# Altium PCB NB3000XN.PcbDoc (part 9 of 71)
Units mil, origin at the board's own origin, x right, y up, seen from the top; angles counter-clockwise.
Board outline 9527.56 x 6929.77 mil, 6 copper layers (Top Layer, GND+SHIELD, MidLayer1, MidLayer2, P2 - 3V3+5V0, Bottom Layer), stack 62.375 mil thick; 832 components, 1027 nets, 4655 pads, 4981 vias.
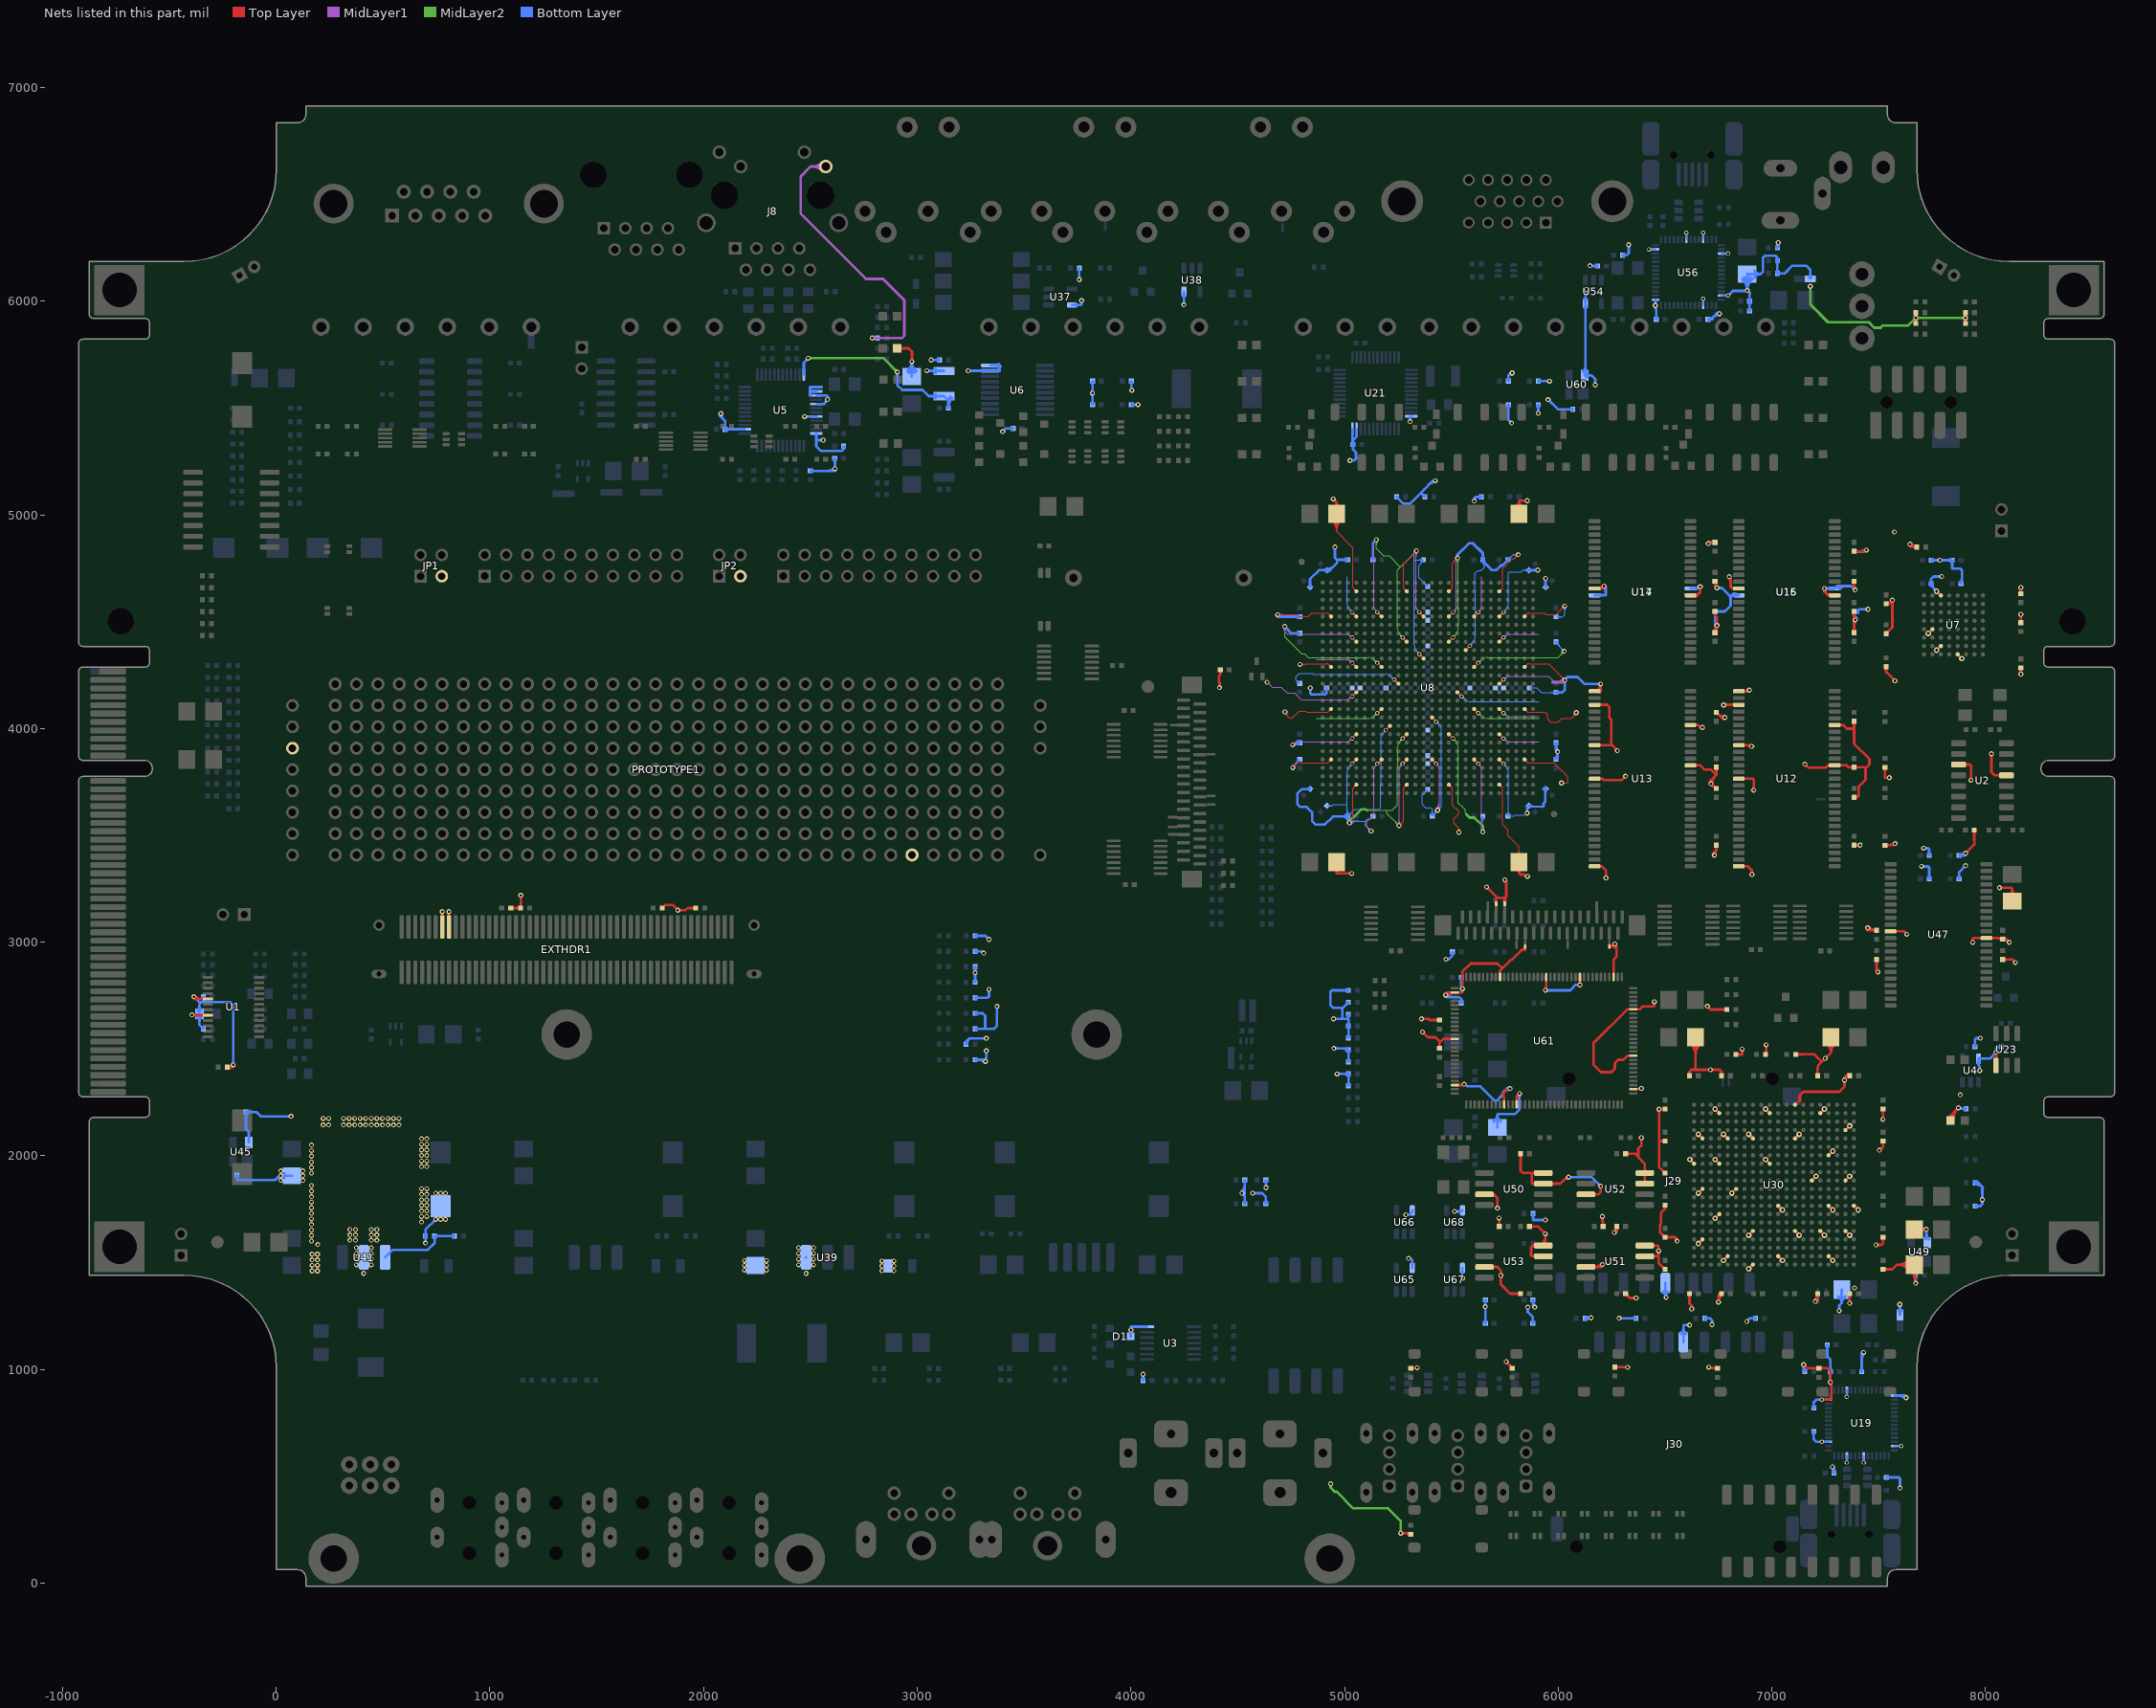
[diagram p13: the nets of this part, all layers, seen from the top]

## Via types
v1: diameter 23, hole 11.81, Top Layer to Bottom Layer, 3672 vias
v2: diameter 26, hole 11.81, Top Layer to Bottom Layer, 461 vias
v3: diameter 19, hole 11.81, Top Layer to Bottom Layer, tented both sides, 396 vias
v4: diameter 23.62, hole 11.81, Top Layer to Bottom Layer, 288 vias
v5: diameter 20, hole 11.81, Top Layer to Bottom Layer, 91 vias
v6: diameter 23, hole 11.81, Top Layer to Bottom Layer, tented both sides, 50 vias
v7: diameter 31, hole 11.81, Top Layer to Bottom Layer, 15 vias
v8: diameter 27.56, hole 11.81, Top Layer to Bottom Layer, tented both sides, 4 vias
v9: diameter 29, hole 11.81, Top Layer to Bottom Layer, 3 vias
v10: diameter 21, hole 11.81, Top Layer to Bottom Layer, 1 vias

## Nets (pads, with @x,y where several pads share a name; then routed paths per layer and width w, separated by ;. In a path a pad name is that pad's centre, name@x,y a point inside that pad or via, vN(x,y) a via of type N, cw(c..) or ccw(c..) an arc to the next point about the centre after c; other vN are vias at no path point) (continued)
3V3: (continued)
  Bottom Layer w12: v1@-385,2739.5 cw(c-385,2726.22) -375.61,2735.61 cw(c-366.22,2745) v1@-379.5,2745 ; v1(-385,2745) -354.99,2714.99 ; C20.1@-369.05,2650.4 cw(c-392.41,2627.04) -359.37,2627.04 cw(c-326.33,2627.04) C20.1@-349.69,2650.4 ; C20.1@-369.05,2679.6 ccw(c-392.41,2702.96) -359.37,2702.96 ccw(c-326.33,2702.96) C20.1@-349.69,2679.6 ; R21.1@-351.1,2604.92 ccw(c-341.18,2614.84) R21.1@-341.18,2600.81 ; R21.1@-349.91,2603.73 cw(c-358.15,2595.49) R21.1@-346.5,2595.49 ; C21.1@-344.78,2740.89 cw(c-354.7,2730.97) -340.67,2730.97 cw(c-326.64,2730.97) C21.1@-336.56,2740.89 ; R21.1@-341.18,2595 -359.37,2613.19 C20.1@-359.37,2665 -359.37,2710.6 -354.99,2714.99 ; C21.1@-340.67,2745 -340.67,2720.71 -340,2720.04 ; v1@-205.36,2429.6 ccw(c-214.75,2438.99) -201.48,2438.99 ccw(c-188.2,2438.99) v1@-197.59,2429.6 ; v1(-201.48,2425.71) -201.48,2705.04 -216.48,2720.04 -340,2720.04 ; R154.2@-187.44,1905.75 cw(c-196.52,1896.67) -183.68,1896.67 cw(c-170.84,1896.67) R154.2@-179.92,1905.75 ; R154.2@-183.68,1910 -183.68,1889.37 -181.68,1887.37 -109.81,1887.37 -4.81,1887.37 14.52,1906.71 14.52,1907.01 v1@21.14,1907.01 ; R98.2@-137.56,2201.24 cw(c-128.48,2192.16) -128.48,2205 cw(c-128.48,2217.84) R98.2@-137.56,2208.76 ; U45.4@-128.05,2063.31 -128.05,2113.05 -141.32,2126.32 R98.2@-141.32,2205 -93.1,2205 -92.81,2204.71 -73.1,2185 v1(70,2185) ; 1.81,1893.99 cw(c21.14,1874.66) v1@21.14,1902 ; v1@25.03,1903.61 cw(c33.23,1895.41) C136.1@33.23,1907.01 ; v1@25.03,1911.39 ccw(c35.61,1921.97) C136.1@35.61,1907.01 ; C136.1@37.85,1895.39 ccw(c21.14,1889.18) v1@21.14,1907.01 ; C136.1@37.85,1918.63 cw(c21.14,1924.83) v1@21.14,1907.01 ; v1@66.11,2181.11 ccw(c56.72,2171.72) 56.72,2185 ccw(c56.72,2198.28) v1@66.11,2188.89 ; C136.1@73.07,1907.01 v1@21.14,1907.01 ; v1@694.64,1595.6 ccw(c684.53,1605.7) 698.82,1605.7 ; R205.2@695.06,1620.75 cw(c685.98,1611.67) 698.82,1611.67 cw(c711.66,1611.67) R205.2@702.58,1620.75 ; R205.2@695.06,1629.25 ccw(c685.98,1638.33) 698.82,1638.33 ccw(c711.66,1638.33) R205.2@702.58,1629.25 ; v1(698.52,1591.71) 698.82,1592 R205.2@698.82,1625 698.82,1654.72 v1(747.01,1702.91) ; 698.82,1604.27 ccw(c711.09,1604.27) v1@702.41,1595.6 ; v1@741.51,1702.91 cw(c728.23,1702.91) 737.62,1693.52 cw(c747.01,1684.14) v1@747.01,1697.41 ; v1@2075.53,5476.54 ccw(c2087.64,5471.49) 2078.36,5462.21 ; v1(2081.52,5474.04) 2081.52,5459.04 2098.52,5442.04 2098.67,5442.04 2100.67,5440.04 C50.2@2100.67,5400 2102.09,5401.42 U5.14@2193.54,5401.42 ; v1@2086.6,5471.92 ccw(c2105.52,5464.03) 2091.02,5449.54 ; C50.2@2096.56,5404.11 ccw(c2086.64,5414.03) 2100.67,5414.03 ccw(c2114.7,5414.03) C50.2@2104.78,5404.11 ; C50.2@2104.78,5395.89 cw(c2118.12,5382.55) 2118.12,5401.42 ; v1@2470.52,5458.37 v1(2472.62,5460.47) U5.44@2528.19,5460.47 ; v1@2476.51,5456.58 cw(c2485.9,5447.19) 2485.9,5460.47 cw(c2485.9,5473.75) v1@2476.51,5464.36 ; U39.3@2479.81,1525.19 U39.3@2480,1525 ; 2498.52,5558.9 2498.52,5578.58 ; 2498.52,5563.77 cw(c2519.48,5563.77) 2504.66,5578.58 cw(c2519.48,5593.4) 2498.52,5593.4 ; 2498.52,5573.71 ccw(c2519.48,5573.71) U5.39@2504.66,5558.9 ; 2498.52,5583.45 cw(c2519.48,5583.45) U5.37@2504.66,5598.27 ; R50.2@2500,5206.18 2605.33,5206.18 v1(2615.19,5216.04) 2615.19,5264.14 C51.2@2614.33,5265 ; R50.2@2504.25,5202.42 cw(c2513.33,5193.34) 2513.33,5206.18 cw(c2513.33,5219.02) R50.2@2504.25,5209.94 ; U5.48@2527.52,5381.73 2527.52,5355 ; U5.41@2528.19,5519.53 2564.53,5519.53 v1(2580,5540.19) 2580,5555 2576.1,5558.9 U5.39@2528.19,5558.9 ; U5.38@2528.19,5578.58 2498.52,5578.58 ; U5.37@2551.71,5598.27 U5.37@2528.19,5598.27 2498.52,5598.27 2498.52,5578.58 ; v1@2556.11,5346.3 ccw(c2546.72,5336.92) 2546.72,5350.19 ccw(c2546.72,5363.47) v1@2556.11,5354.08 ; v1(2560,5350.19) 2532.33,5350.19 2527.52,5355 ; v1@2574.56,5539.41 cw(c2561.41,5537.52) 2572.04,5529.56 cw(c2582.67,5521.61) v1@2580.78,5534.75 ; 2578.11,5206.18 ccw(c2578.11,5253.12) 2611.3,5219.93 ccw(c2601.91,5229.32) 2615.19,5229.32 ccw(c2628.47,5229.32) v1@2619.08,5219.93 ; 2582.75,5552.25 cw(c2572.9,5542.4) v1@2586.21,5538.27 ; 2607.08,5206.18 ccw(c2607.08,5224.15) v1@2619.79,5211.44 ; C51.2@2610.22,5260.89 cw(c2598.23,5248.9) 2615.19,5248.9 ; 2615.19,5253.05 cw(c2626.28,5253.05) C51.2@2618.44,5260.89 ; R59.2@2652.42,5318.25 cw(c2643.34,5309.17) 2656.18,5309.17 cw(c2669.02,5309.17) R59.2@2659.94,5318.25 ; R59.2@2656.18,5322.5 2656.18,5308.37 2647.85,5300.04 2548.52,5300.04 2527.52,5321.04 2527.52,5355 ; v1(2789.7,5828) R57.2@2813.82,5828 ; v1@2793.59,5824.11 cw(c2802.98,5814.72) 2802.98,5828 cw(c2802.98,5841.28) v1@2793.59,5831.89 ; C49.1@2954.13,5674.03 ccw(c2919.27,5717.51) v1@2975,5717.51 ; C49.1@2961.63,5664.67 ccw(c2939.31,5692.51) 2975,5692.51 ccw(c3010.69,5692.51) C49.1@2988.37,5664.67 ; v1@2971.3,5713.82 cw(c2962.37,5704.89) 2975,5704.89 ; C49.1@2975,5647.99 v1@2975,5717.52 ; 2975,5703.97 cw(c2988.93,5703.97) v1@2979.08,5713.82 ; C49.1@2995.87,5674.03 cw(c3030.73,5717.51) v1@2975,5717.51 ; v1@3045,5675 3124.06,5675 L2.1@3125,5674.06 ; v1@3048.89,5671.3 cw(c3057.81,5662.38) 3057.81,5675 ; v1@3048.89,5679.08 ccw(c3058.75,5688.94) 3058.75,5675 ; 3060.15,5675 cw(c3060.15,5638.74) L2.1@3085.8,5664.38 ; 3064.72,5675 ccw(c3064.72,5704.81) L2.1@3085.8,5683.73 ; v1(3065,5725.19) C52.2@3104.33,5725 ; v1@3068.87,5721.29 cw(c3078.21,5711.85) 3078.28,5725.13 cw(c3078.34,5738.41) v1@3068.91,5729.06 ; C52.2@3100.2,5720.91 ccw(c3090.23,5711.04) 3090.3,5725.07 ccw(c3090.37,5739.1) C52.2@3100.24,5729.13 ; R226.2@3228.82,2522.5 3228.82,2533.86 3245,2550.04 ; R226.2@3234.14,2523.09 cw(c3271.24,2523.8) 3245,2550.04 ; v1(3238,5674.57) U6.19@3341.06,5674.57 3384.19,5674.57 3386.19,5676.57 3386.19,5698.49 3384.52,5700.16 U6.20@3341.06,5700.16 ; v1@3241.89,5670.68 cw(c3251.28,5661.29) 3251.28,5674.57 cw(c3251.28,5687.84) v1@3241.89,5678.46 ; v1@3267.3,2853.49 cw(c3257.93,2844.12) 3271.18,2844.12 ; v1@3267.3,2861.26 ccw(c3257.93,2870.63) 3271.18,2870.63 ; R224.2@3267.42,2816.75 ccw(c3258.34,2825.83) 3271.18,2825.83 ccw(c3284.02,2825.83) R224.2@3274.94,2816.75 ; R219.2@3267.42,2880.75 cw(c3258.34,2871.67) 3271.18,2871.67 cw(c3284.02,2871.67) R219.2@3274.94,2880.75 ; R232.2@3271.18,2450 v1@3319.48,2450 ; R227.2@3271.18,2595 3313.9,2595 ; R225.2@3271.18,2667.5 3305.92,2667.5 3317.92,2655.5 ; R218.2@3271.18,2740 3330,2740 3336.19,2746.19 v1(3336.19,2779.37) v1@3331.86,2775.04 ; R224.2@3271.18,2812.5 v1(3271.19,2857.37) R219.2@3271.18,2885 ; 3271.18,2844.07 cw(c3284.49,2844.07) v1@3275.08,2853.49 ; 3271.18,2870.67 ccw(c3284.49,2870.67) v1@3275.08,2861.26 ; R217.2@3271.18,2957.5 3302.73,2957.5 v1(3311.19,2949.04) ; R216.2@3271.18,3030 3319.23,3030 v1(3336.19,3013.04) ; R232.2@3274.94,2446.24 cw(c3284.02,2437.16) 3284.02,2450 cw(c3284.02,2462.84) R232.2@3274.94,2453.76 ; R227.2@3274.94,2591.24 cw(c3284.02,2582.16) 3284.02,2595 cw(c3284.02,2607.84) R227.2@3274.94,2598.76 ; R225.2@3274.94,2663.74 cw(c3284.02,2654.66) 3284.02,2667.5 cw(c3284.02,2680.34) R225.2@3274.94,2671.26 ; R218.2@3274.94,2736.24 cw(c3284.02,2727.16) 3284.02,2740 cw(c3284.02,2752.84) R218.2@3274.94,2743.76 ; R217.2@3274.94,2953.74 cw(c3284.02,2944.66) 3284.02,2957.5 cw(c3284.02,2970.34) R217.2@3274.94,2961.26 ; R216.2@3274.94,3026.24 cw(c3284.02,3017.16) 3284.02,3030 cw(c3284.02,3042.84) R216.2@3274.94,3033.76 ; 3286.23,2450 cw(c3286.23,2408.41) v1@3315.64,2437.82 ; v1@3315.64,2445.6 ccw(c3296.59,2464.64) 3323.52,2464.64 ; 3317.86,2655.37 3317.86,2598.96 3313.9,2595 ; v1(3319.52,2441.71) 3319.52,2450.04 v1@3319.48,2450 ; v1@3319.64,2487.82 cw(c3310.25,2478.43) 3323.52,2478.43 cw(c3336.8,2478.43) v1@3327.41,2487.82 ; v1@3319.64,2546.15 ccw(c3310.25,2536.76) 3310.25,2550.04 ccw(c3310.25,2563.32) v1@3319.64,2553.93 ; v1(3323.52,2491.71) 3323.52,2454.04 v1@3319.48,2450 ; v1(3323.52,2550.04) 3245,2550.04 ; v1@3330.69,3013.04 ccw(c3317.41,3013.04) 3326.8,3022.43 ccw(c3336.19,3031.82) v1@3336.19,3018.54 ; v1@3332.3,2775.49 cw(c3322.91,2766.1) 3336.19,2766.1 cw(c3349.47,2766.1) v1@3340.08,2775.49 ; v1@3369.64,2696.15 cw(c3360.25,2686.76) 3373.52,2686.76 cw(c3386.8,2686.76) v1@3377.41,2696.15 ; U6.20@3373,5697.74 cw(c3357.94,5673.84) 3386.19,5673.84 ; v1(3373.52,2700.04) 3373.52,2608.52 3360,2595 3313.9,2595 ; U6.20@3375.37,5697.43 cw(c3380.01,5682.31) 3391.19,5693.49 ; U6.20@3379.4,5707.89 cw(c3371.65,5695.59) 3386.19,5695.59 ; v1(3400,5390) 3415,5405 C54.2@3449.33,5405 ; C54.2@3445.22,5400.89 ccw(c3435.3,5390.97) 3435.3,5405 ccw(c3435.3,5419.03) C54.2@3445.22,5409.11 ; U37.5@3725.12,5982.6 3765.52,5982.6 3769.52,5986.6 v1(3769.52,6003.37) ; U37.5@3742.02,5978.49 cw(c3751.94,5968.57) 3751.94,5982.6 cw(c3751.94,5996.63) U37.5@3742.02,5986.71 ; v1@3754.79,6105.21 ccw(c3745.4,6114.6) 3758.68,6114.6 ccw(c3771.96,6114.6) v1@3762.57,6105.21 ; v1(3758.68,6101.32) R195.2@3758.68,6155 ; v1@3765.64,5999.49 cw(c3756.25,5990.1) 3769.52,5990.1 cw(c3782.8,5990.1) v1@3773.41,5999.49 ; C244.1@3816.28,5520.29 ccw(c3806.36,5530.21) 3820.39,5530.21 ccw(c3834.42,5530.21) C244.1@3824.5,5520.29 ; C243.1@3816.28,5622.07 cw(c3806.36,5612.15) 3820.39,5612.15 cw(c3834.42,5612.15) C243.1@3824.5,5622.07 ; v1@3816.5,5566.3 cw(c3807.11,5556.92) 3820.39,5556.92 cw(c3833.66,5556.92) v1@3824.28,5566.3 ; v1@3816.5,5574.08 ccw(c3807.11,5583.47) 3820.39,5583.47 ccw(c3833.66,5583.47) v1@3824.28,5574.08 ; C244.1@3820.39,5516.18 v1(3820.39,5570.19) C243.1@3820.39,5626.18 ; C229.1@3997.62,5622.07 cw(c3987.7,5612.15) 4001.73,5612.15 cw(c4015.75,5612.15) C229.1@4005.83,5622.07 ; D1.3@3999.21,1155 v1@3999.21,1175.04 ; v1(4000,1185) 4000,1200 U3.14@4076.5,1200 ; C259.1@4001.72,5516.18 v1@4033.82,5516.18 ; 4001.73,5603.41 ccw(c4024.56,5603.41) v1@4008.41,5587.26 ; C229.1@4001.72,5626.18 v1@4001.73,5586.17 ; C259.1@4005.83,5512.07 cw(c4015.75,5502.15) 4015.75,5516.18 cw(c4015.75,5530.21) C259.1@4005.83,5520.29 ; 4020.08,5516.18 ccw(c4020.08,5530.12) v1@4029.93,5520.26 ; 4021.01,5516.18 cw(c4021.01,5503.56) v1@4029.93,5512.48 ; C37.2@4053.22,953.11 ccw(c4043.3,963.03) 4057.33,963.03 ccw(c4071.36,963.03) C37.2@4061.44,953.11 ; v1@4053.44,973.78 cw(c4044.05,964.39) 4057.33,964.39 cw(c4070.61,964.39) v1@4061.22,973.78 ; C37.2@4057.33,949 v1(4057.33,977.67) ; U38.5@4244.33,6027.98 cw(c4234.41,6018.06) 4248.44,6018.06 cw(c4262.47,6018.06) U38.5@4252.55,6027.98 ; v1@4244.47,5986.95 ccw(c4234.88,5996.53) 4248.44,5996.53 ; v1(4248.36,5983.06) 4248.44,5983.14 U38.5@4248.44,6044.88 ; 4248.44,5996.13 ccw(c4261.44,5996.13) v1@4252.25,5986.95 ; v1@4516.11,1828.89 ccw(c4475.18,1869.82) 4533.06,1869.82 ; v1(4520,1825) 4533.06,1811.94 ; v1@4524.6,1820.4 ccw(c4504.15,1840.85) 4533.06,1840.85 ; C216.1@4528.95,1780.29 ccw(c4519.03,1790.21) 4533.06,1790.21 ccw(c4547.09,1790.21) C216.1@4537.17,1780.29 ; C232.1@4528.95,1882.07 cw(c4519.03,1872.15) 4533.06,1872.15 cw(c4547.09,1872.15) C232.1@4537.17,1882.07 ; C216.1@4533.06,1776.18 4533.06,1811.94 ; C232.1@4533.06,1886.18 4533.06,1825 4533.06,1811.94 ; v1(4570,1825) 4615,1825 4631.72,1808.28 C252.1@4631.72,1776.18 ; v1@4573.89,1821.11 cw(c4583.28,1811.72) 4583.28,1825 cw(c4583.28,1838.28) v1@4573.89,1828.89 ; C252.1@4627.62,1780.29 ccw(c4617.7,1790.21) 4631.72,1790.21 ccw(c4645.75,1790.21) C252.1@4635.83,1780.29 ; C251.1@4627.62,1882.07 cw(c4617.7,1872.15) 4631.72,1872.15 cw(c4645.75,1872.15) C251.1@4635.83,1882.07 ; v1@4630,1852 4631,1853 4631.72,1853.72 C251.1@4631.72,1886.18 ; 4631.72,1867.36 ccw(c4649.36,1867.36) v1@4636.89,1854.89 ; v1@4682.26,4528.78 ccw(c4694.61,4541.13) 4694.61,4523.66 ; v1(4686.86,4533.37) 4696.57,4523.66 C304.1@4790,4523.66 ; v1@4690.75,4537.26 ccw(c4723.58,4570.1) 4723.58,4523.66 ; v1@4720.19,4472.87 cw(c4720.19,4459.6) 4729.58,4468.99 cw(c4738.97,4478.37) v1@4725.69,4478.37 ; v1(4720.19,4478.37) 4739.19,4459.37 4739.19,4456.22 4748.52,4446.89 C320.1@4790,4446.89 ; v1(4757.52,3816.71) v1@4757.52,3824.04 ; v1@4758.52,3925.04 4765.19,3925.04 4765.19,3925.11 4773.19,3933.11 ; v1@4764.79,3924.71 cw(c4778.22,3911.27) C323.1@4787.24,3928 ; 4773.61,3933.53 cw(c4787.92,3919.22) C323.1@4790.92,3939.23 ; 4776.18,3936.1 cw(c4786.21,3926.08) C323.1@4792.94,3938.56 ; C320.1@4785.89,4442.78 ccw(c4775.97,4432.86) 4775.97,4446.89 ccw(c4775.97,4460.92) C320.1@4785.89,4451 ; C304.1@4785.89,4519.55 ccw(c4775.97,4509.63) 4775.97,4523.66 ccw(c4775.97,4537.69) C304.1@4785.89,4527.77 ; 4822.74,3716.71 ccw(c4822.74,3733.64) C327.1@4834.71,3721.67 ; C327.1@4826.84,3716.71 cw(c4826.84,3705.58) C327.1@4834.71,3713.45 ; C310.1@4834.71,4666.55 ccw(c4824.79,4676.47) 4838.82,4676.47 ccw(c4852.85,4676.47) C310.1@4842.93,4666.55 ; C327.1@4838.82,3717.56 4838.82,3716.71 4799.86,3716.71 4780,3696.85 4780,3644.9 4791.52,3633.37 4823.52,3633.37 4848.52,3608.37 4848.52,3566.71 4865.19,3550.04 4906.86,3550.04 4945.38,3588.57 C331.1@5003.57,3588.57 ; C310.1@4838.82,4662.44 4838.82,4700.04 ; 4838.86,4700.04 4880.52,4741.71 C294.1@4917.56,4741.71 ; v4(4840,4190) 4840,4165 4845,4160 4910,4160 4915.59,4165.59 C318.1@4915.59,4190 ; C294.1@4902.26,4741.71 cw(c4902.26,4725.88) C294.1@4913.45,4737.07 ; C294.1@4904.8,4741.71 ccw(c4904.8,4753.94) C294.1@4913.45,4745.29 ; C294.1@4917.56,4734.99 ccw(c4917.56,4752.94) C294.1@4930.25,4740.25 ; C294.1@4917.56,4741.18 4931.18,4741.18 4965,4775 4965,4790 ; C294.1@4917.56,4746.99 ccw(c4917.56,4793.91) 4950.73,4760.73 ; v1(4950,2503) 5011.27,2503 R240.2@5018.82,2495.45 R241.2@5018.82,2439.55 ; v1@4951.11,4846.11 cw(c4941.72,4836.72) 4955,4836.72 cw(c4968.28,4836.72) v1@4958.89,4846.11 ; v1@4953.89,2499.11 cw(c4963.28,2489.72) 4963.28,2503 cw(c4963.28,2516.28) v1@4953.89,2506.89 ; v1@4959.52,4846.04 4955.56,4850 v1(4955,4850) 4955,4800 4965,4790 ; v1(4965.19,2383.37) 4994.19,2383.37 4994.45,2383.64 R242.2@5018.82,2383.64 R243.2@5018.82,2327.73 R243.2@5018.82,2329.67 ; v1@4969.08,2379.49 cw(c4978.47,2370.1) 4978.47,2383.37 cw(c4978.47,2396.65) v1@4969.08,2387.26 ; 4986.86,2641.71 v1(4948.52,2641.71) 5017.11,2641.71 5018.82,2640 ; 4988.95,2503 cw(c4988.95,2466.08) R240.2@5015.06,2492.19 ; 4989.5,2645.73 4989.5,2686.91 ; 4997.51,3588.57 ccw(c4997.51,3607.49) C331.1@5010.89,3594.11 ; C331.1@5006.9,3585.23 cw(c4980.04,3558.37) v1@5018.02,3558.37 ; R236.2@5008.9,2709.17 cw(c5018.82,2699.25) R236.2@5018.82,2713.28 ; R236.2@5010.09,2710.36 ccw(c5001.85,2718.6) R236.2@5013.5,2718.6 ; C308.1@5010.89,4785.89 ccw(c5000.97,4775.97) 5000.97,4790 ccw(c5000.97,4804.03) C308.1@5010.89,4794.11 ; C331.1@5015,3590 5013.56,3588.57 C331.1@5003.57,3588.57 ; C308.1@5015,4790 4965,4790 ; R243.2@5015.06,2331.98 ccw(c5005.98,2341.06) 5018.82,2341.06 ccw(c5031.66,2341.06) R243.2@5022.58,2331.98 ; R242.2@5015.06,2379.38 cw(c5005.98,2370.3) 5018.82,2370.3 cw(c5031.66,2370.3) R242.2@5022.58,2379.38 ; R242.2@5015.06,2379.87 ccw(c5005.98,2370.8) 5005.98,2383.64 ccw(c5005.98,2396.48) R242.2@5015.06,2387.4 ; R241.2@5015.06,2443.8 ccw(c5005.98,2452.88) 5018.82,2452.88 ccw(c5031.66,2452.88) R241.2@5022.58,2443.8 ; R240.2@5015.06,2491.2 cw(c5005.98,2482.12) 5018.82,2482.12 cw(c5031.66,2482.12) R240.2@5022.58,2491.2 ; R239.2@5015.06,2555.62 ccw(c5005.98,2564.7) 5018.82,2564.7 ccw(c5031.66,2564.7) R239.2@5022.58,2555.62 ; R238.2@5015.06,2603.02 cw(c5005.98,2593.94) 5018.82,2593.94 cw(c5031.66,2593.94) R238.2@5022.58,2603.02 ; R238.2@5015.06,2611.53 ccw(c5005.98,2620.61) 5018.82,2620.61 ccw(c5031.66,2620.61) R238.2@5022.58,2611.53 ; R237.2@5015.06,2658.93 cw(c5005.98,2649.85) 5018.82,2649.85 cw(c5031.66,2649.85) R237.2@5022.58,2658.93 ; R260.2@5015.06,2771.24 ccw(c5005.98,2762.16) 5005.98,2775 ccw(c5005.98,2787.84) R260.2@5015.06,2778.76 ; R242.2@5018.82,2383.82 R242.2@5020,2385 ; R239.2@5018.82,2551.36 R238.2@5018.82,2607.27 5018.82,2640 ; R237.2@5018.82,2663.18 5018.82,2640 ; R236.2@5018.82,2719.09 4989.5,2689.77 4989.5,2686.91 ; R260.2@5018.82,2775 4940,2775 4933.5,2768.5 4933.5,2706.09 4946.09,2693.5 4982.91,2693.5 4989.5,2686.91 ; v1@5023.52,3568.61 5008.57,3583.57 C331.1@5003.57,3588.57 ; v4(5025,5255) 5045,5255 5053.36,5263.36 5053.36,5292.28 5039.33,5306.31 C96.1@5039.33,5330 ; v4@5029.11,5250.89 cw(c5039.03,5240.97) 5039.03,5255 cw(c5039.03,5269.03) v4@5029.11,5259.11 ; C96.1@5035.22,5325.89 cw(c5025.3,5315.97) 5039.33,5315.97 cw(c5053.36,5315.97) C96.1@5043.44,5325.89 ; C96.1@5035.22,5334.11 ccw(c5025.3,5344.03) 5039.33,5344.03 ccw(c5053.36,5344.03) 5043.44,5334.11 cw(c5059.63,5350.3) 5036.73,5350.3 ; U21.24@5036.73,5402.68 5036.73,5332.6 C96.1@5039.33,5330 ; U21.23@5056.42,5402.68 5056.42,5366.42 5039.33,5349.33 C96.1@5039.33,5330 ; C292.1@5129,4794.11 ccw(c5119.08,4804.03) 5133.11,4804.03 ccw(c5147.14,4804.03) C292.1@5137.22,4794.11 ; C292.1@5133.11,4790 5133.11,4867.96 v1(5149.52,4884.37) ; v1@5144.02,4884.37 cw(c5130.75,4884.37) 5140.14,4874.99 cw(c5149.52,4865.6) v1@5149.52,4878.87 ; C298.1@5193.15,4190 C298.1@5193.15,4190.36 ; v3@5232.16,4229.37 v3(5232.52,4229.37) ; R77.2@5243.82,5085 5243.82,5081.37 5247.82,5077.37 5249.82,5077.37 5274.49,5052.71 5306.19,5052.71 5373.52,5120.04 5403.52,5150.04 5413.48,5160 v4(5425,5160) ; R77.2@5249.14,5084.51 ccw(c5264.71,5084.51) R77.2@5253.7,5073.49 ; v1(5287.34,1724.1) 5287.34,1724.38 5287.96,1725 5305,1725 5317.4,1737.4 U66.5@5317.4,1745.12 U66.5@5317.28,1745 ; v1(5300,1520) 5310,1520 5317.4,1512.6 U65.5@5317.4,1475.12 ; v1@5302.97,5440.6 ccw(c5293.26,5450.3) 5306.99,5450.3 ; v1(5306.86,5436.71) 5306.99,5436.71 5306.99,5456.4 U21.12@5312.32,5461.73 ccw(c5325.2,5448.86) 5306.99,5448.86 ; 5306.99,5449.67 ccw(c5319.82,5449.67) v1@5310.75,5440.6 ; 5360,5100 5361.32,5100 R76.2@5376.32,5085 ; R76.2@5366.4,5094.92 ccw(c5376.32,5104.84) R76.2@5376.32,5090.81 ; R76.2@5367.59,5093.73 cw(c5359.35,5085.49) R76.2@5371,5085.49 ; 5397.77,5144.28 cw(c5421.96,5120.09) v4@5424.56,5154.21 ; v1@5469.26,2748.11 ccw(c5484.72,2763.57) 5484.72,2741.71 ; v1(5473.86,2752.71) 5484.86,2741.71 5538.39,2741.71 5546.73,2733.37 C258.1@5546.72,2715 ; v4(5475,2920) 5488.52,2920 5504.87,2936.35 R73.2@5504.87,2955 ; v1@5477.75,2756.6 ccw(c5513.69,2792.54) 5513.69,2741.71 ; R73.2@5501.11,2950.75 cw(c5492.03,2941.67) 5504.87,2941.67 cw(c5517.72,2941.67) R73.2@5508.64,2950.75 ; v1(5515,1740) 5547.28,1740 U68.5@5552.4,1745.12 ; v1(5528.86,4798.37) 5528.86,4813.71 5581.86,4866.71 5595.52,4866.71 5603.29,4866.71 5646.89,4823.11 5646.89,4815.34 C291.1@5646.89,4790 ; C258.1@5542.62,2719.11 ccw(c5532.7,2729.03) 5546.73,2729.03 ccw(c5560.75,2729.03) C258.1@5550.83,2719.11 ; C257.1@5542.62,2830.89 cw(c5532.7,2820.97) 5546.73,2820.97 cw(c5560.75,2820.97) C257.1@5550.83,2830.89 ; 5546.73,2807.71 ccw(c5577.53,2807.71) v1@5555.75,2785.93 ; C257.1@5546.72,2835 5546.73,2787.17 v1(5551.86,2782.04) ; v1(5560,2335) 5560,2336.47 5563.53,2336.47 5574.96,2325.04 5636.86,2325.04 5703.52,2258.37 5712.26,2258.37 5740.19,2286.3 5740.19,2295.04 5760.52,2315.37 5779.52,2315.37 5779.15,2315 v1(5775,2315) ; v1(5606.86,5065.04) 5606.86,5076.86 5615,5085 R70.2@5641.32,5085 ; v1@5611.85,5067.35 cw(c5626.08,5073.91) 5615,5085 ; R70.2@5637.56,5081.24 ccw(c5628.48,5072.16) 5628.48,5085 ccw(c5628.48,5097.84) R70.2@5637.56,5088.76 ; C291.1@5642.78,4794.11 ccw(c5632.86,4804.03) 5646.89,4804.03 ccw(c5660.92,4804.03) C291.1@5651,4794.11 ; C291.1@5646.89,4785.01 5654,4777.9 5690.19,4741.71 ; C291.1@5652.7,4790 ccw(c5678.78,4790) 5660.34,4771.56 ; C235.1@5654.94,1220.29 ccw(c5644.67,1230.55) 5659.19,1230.55 ; C219.1@5654.94,1322.07 cw(c5644.67,1311.8) 5659.19,1311.8 ; v1@5655.3,1289.82 cw(c5645.91,1280.43) 5659.19,1280.43 cw(c5672.47,1280.43) v1@5663.08,1289.82 ; v1@5655.3,1297.6 ccw(c5645.91,1306.99) 5659.19,1306.99 ccw(c5672.47,1306.99) v1@5663.08,1297.6 ; v1@5656.86,1291.37 5659.05,1293.56 v1@5659.05,1293.71 ; C235.1@5659.05,1216.18 5659.19,1216.32 v1(5659.19,1293.71) 5659.19,1326.03 C219.1@5659.05,1326.18 ; 5659.19,1229.86 ccw(c5672.73,1229.86) C235.1@5663.16,1220.29 ; 5659.19,1312.49 cw(c5672.73,1312.49) C219.1@5663.16,1322.07 ; 5673.52,4758.37 5690.19,4741.71 ; C185.1@5697.38,2161.33 ccw(c5677.66,2193.04) 5715,2193.04 ; C185.1@5715,2132.99 5715,2193.04 ; C185.1@5732.62,2161.33 cw(c5752.34,2193.04) 5715,2193.04 ; 5740.26,2295.11 cw(c5775,2260.37) v1@5775,2309.5 ; C307.1@5759.19,4790 cw(c5745.16,4790) 5755.08,4780.08 cw(c5765,4770.16) C307.1@5765,4784.19 ; 5760.74,2315.6 cw(c5775,2301.34) v1@5775,2321.5 ; C256.1@5762.62,5512.07 cw(c5752.7,5502.15) 5766.72,5502.15 cw(c5780.75,5502.15) C256.1@5770.83,5512.07 ; C255.1@5762.62,5630.29 ccw(c5752.7,5640.21) 5766.72,5640.21 ccw(c5780.75,5640.21) C255.1@5770.83,5630.29 ; C307.1@5765,4790 5738.04,4763.04 5731.86,4763.04 5710.52,4741.71 5690.19,4741.71 ; 5766.54,5651.54 cw(c5785,5633.09) v4@5785,5659.19 ; C256.1@5766.72,5516.18 5766.72,5445.17 v1(5781.86,5430.04) ; C255.1@5766.72,5626.18 5766.72,5651.72 v4@5780.49,5665.49 ; v1@5815.3,2287.82 cw(c5805.91,2278.43) 5819.19,2278.43 cw(c5832.47,2278.43) v1@5823.08,2287.82 ; v1(5819.19,2291.71) 5819.19,2217.03 5798.52,2196.36 5718.51,2196.36 5715.19,2193.04 5715,2193.04 ; v1@5853.64,1287.82 cw(c5844.25,1278.43) 5857.52,1278.43 cw(c5870.8,1278.43) v1@5861.41,1287.82 ; v4(5855,3605) 5855,3631.38 C324.1@5862.44,3638.82 ; v1(5857.52,1291.71) 5857.52,1269.33 5881.72,1245.13 C250.1@5881.72,1216.18 ; C293.1@5862.44,4741.18 5893.33,4741.18 5905,4741.18 5910.33,4741.18 v1@5910.86,4741.71 ; C293.1@5866.55,4737.07 cw(c5876.47,4727.15) 5876.47,4741.18 cw(c5876.47,4755.21) C293.1@5866.55,4745.29 ; C250.1@5877.62,1220.29 ccw(c5867.7,1230.21) 5881.72,1230.21 ccw(c5895.75,1230.21) C250.1@5885.83,1220.29 ; C249.1@5877.62,1322.07 cw(c5867.7,1312.15) 5881.72,1312.15 cw(c5895.75,1312.15) C249.1@5885.83,1322.07 ; R158.2@5878.48,1725.75 cw(c5869.39,1716.67) 5882.24,1716.67 cw(c5895.08,1716.67) R158.2@5886,1725.75 ; C249.1@5881.72,1325.42 ccw(c5923.91,1325.42) v1@5894.08,1295.6 ; C249.1@5881.72,1326.18 5881.72,1300.17 v1(5890.19,1291.71) ; R158.2@5882.24,1730 5882.24,1700.04 v1(5940.19,1700.04) ; 5890.45,4741.18 ccw(c5890.45,4756.26) v1@5901.11,4745.6 ; 5892.99,4741.18 cw(c5892.99,4729.7) v1@5901.11,4737.82 ; v1@5896.19,4741.37 v1@5896.52,4741.71 ; C226.1@5902.62,5512.07 cw(c5892.7,5502.15) 5906.73,5502.15 cw(c5920.75,5502.15) C226.1@5910.83,5512.07 ; v1@5902.84,5479.12 ccw(c5893.45,5488.51) 5906.73,5488.51 ccw(c5920,5488.51) v1@5910.61,5479.12 ; v1@5906.73,5475.04 v1(5906.73,5475.23) C226.1@5906.72,5516.18 ; C225.1@5906.72,5626.18 v1(5959.72,5626.18) ; C225.1@5910.83,5622.07 cw(c5920.75,5612.15) 5920.75,5626.18 cw(c5920.75,5640.21) C225.1@5910.83,5630.29 ; 5928.52,3633.37 5931.86,3636.71 5931.86,3649.89 5940.02,3658.05 5940.02,3709.39 5936.52,3712.9 C325.1@5931.86,3717.56 ; v1@5936.3,1696.15 ccw(c5926.91,1686.76) 5926.91,1700.04 ccw(c5926.91,1713.32) v1@5936.3,1703.93 ; 5940.02,3700.74 cw(c5958.01,3700.74) C325.1@5945.29,3713.45 ; v1(5940.19,2775.04) 6056.86,2775.04 6082.52,2800.71 v1(6101.86,2800.71) ; 5940.19,4678.86 ccw(c5957.6,4678.86) C309.1@5945.29,4666.55 ; 5940.19,4687.35 cw(c5956.88,4687.35) v1@5945.08,4699.15 ; C325.1@5941.18,3717.56 C325.1@5941.18,3725.04 ; C309.1@5941.18,4662.44 5941.18,4663.37 5940.19,4663.37 5940.19,4702.04 v1(5941.19,4703.04) ; v1@5944.08,2771.15 cw(c5953.47,2761.76) 5953.47,2775.04 cw(c5953.47,2788.32) v1@5944.08,2778.93 ; v1@5952.77,5534.5 cw(c5952.77,5521.22) 5962.16,5530.61 cw(c5971.55,5540) v1@5958.27,5540 ; v1(5952.77,5540) 5997.77,5495 R271.2@6068.82,5495 ; v1@5955.83,5622.29 ccw(c5946.44,5612.9) 5946.44,5626.18 ccw(c5946.44,5639.45) v1@5955.83,5630.07 ; C321.1@5985.89,3860.45 ccw(c5958.61,3887.73) v1@5997.19,3887.73 ; C305.1@5985.89,3929 cw(c5975.97,3919.08) 5990,3919.08 cw(c6004.03,3919.08) C305.1@5994.11,3929 ; C321.1@5990,3856.34 5997.19,3863.53 v1(5997.19,3891.71) 5990,3898.9 C305.1@5990,3933.11 ; C305.1@5990,3922.34 ccw(c6027.83,3922.34) v1@6001.08,3895.6 ; v1@5993.3,3887.82 cw(c5983.91,3878.43) 5997.19,3878.43 cw(c6010.47,3878.43) v1@6001.08,3887.82 ; C334.1@5994.11,4165.22 cw(c6004.03,4155.3) 6004.03,4169.33 cw(c6004.03,4183.36) C334.1@5994.11,4173.44 ; C334.1@5995.71,4175.04 C334.1@5990,4169.33 6019.33,4169.33 6030.52,4180.52 v1(6030.52,4227.71) 6044.52,4241.71 6090.19,4241.71 6123.52,4208.37 v1(6198.52,4208.37) ; v1@6026.64,4223.82 cw(c6017.25,4214.43) 6030.52,4214.43 cw(c6043.8,4214.43) v1@6034.41,4223.82 ; v1(6048.52,1900.04) 6156.86,1900.04 v1(6198.52,1858.37) ; v1@6052.41,1896.15 cw(c6061.8,1886.76) 6061.8,1900.04 cw(c6061.8,1913.32) v1@6052.41,1903.93 ; R271.2@6065.06,5491.24 ccw(c6055.98,5482.16) 6055.98,5495 ccw(c6055.98,5507.84) R271.2@6065.06,5498.76 ; v1@6097.97,2796.82 ccw(c6088.58,2787.43) 6088.58,2800.71 ccw(c6088.58,2813.99) v1@6097.97,2804.6 ; U60.4@6116.16,5670.45 ccw(c6088.8,5697.82) 6127.5,5697.82 ; U54.5@6123.49,5972.98 cw(c6113.81,5963.3) 6127.5,5963.3 ; U54.5@6123.49,6006.79 ccw(c6113.57,6016.71) 6127.6,6016.71 ccw(c6141.63,6016.71) U54.5@6131.71,6006.79 ; R254.1@6126.18,1240 6146.86,1240 v1@6148.52,1241.67 ; 6127.5,5683.09 ccw(c6145.37,5683.09) U60.4@6132.73,5670.45 ; 6127.5,5962.82 cw(c6141.86,5962.82) U54.5@6131.71,5972.98 ; v1@6127.97,6051.82 cw(c6118.58,6042.43) 6131.86,6042.43 cw(c6145.14,6042.43) v1@6135.75,6051.82 ; R254.1@6129.94,1236.24 cw(c6139.02,1227.16) 6139.02,1240 cw(c6139.02,1252.84) R254.1@6129.94,1243.76 ; v1(6131.86,6055.71) 6131.86,6029.26 6127.6,6025 U54.5@6127.6,5989.88 6127.5,5989.78 6127.5,5656.36 U60.4@6124.45,5653.31 6156.69,5653.31 6173.52,5636.48 v1(6173.52,5608.37) v1@6170.52,5611.37 ; U60.4@6132.73,5645.02 cw(c6152.73,5625.02) 6152.73,5653.31 cw(c6152.73,5681.59) U60.4@6132.73,5661.59 ; R254.1@6135.79,1240 ccw(c6135.79,1259.11) v1@6149.3,1245.6 ; v1@6148.52,1241.71 v1(6153.19,1241.71) v1@6154.9,1240 ; v1(6148.52,6166.71) 6148.19,6166.71 6148.19,6161.67 6150.88,6164.35 6151.52,6165 C172.2@6184.33,6165 ; v1@6152.41,6170.6 ccw(c6165.93,6184.11) 6165.93,6165 ; v1@6169.64,5612.26 ccw(c6160.25,5621.65) 6173.52,5621.65 ccw(c6186.8,5621.65) v1@6177.41,5612.26 ; U14.33@6170.59,4624.25 6221.98,4624.25 6223.52,4625.79 6223.52,4658.37 ; C172.2@6180.22,6160.89 ccw(c6170.3,6150.97) 6170.3,6165 ccw(c6170.3,6179.03) C172.2@6180.22,6169.11 ; v1@6193.02,1858.37 ccw(c6179.75,1858.37) 6189.13,1867.76 ccw(c6198.52,1877.15) v1@6198.52,1863.87 ; v1@6194.64,4204.49 ccw(c6185.25,4195.1) 6185.25,4208.37 ccw(c6185.25,4221.65) v1@6194.64,4212.26 ; v1@6211.3,4662.82 cw(c6181.79,4633.31) 6223.52,4633.31 ; v1(6285,1240.19) R255.1@6363.82,1240 ; v1@6288.88,1236.3 cw(c6298.25,1226.88) 6298.28,1240.16 cw(c6298.31,1253.44) v1@6288.9,1244.07 ; C168.1@6300.67,6215 6319.86,6215 6329.86,6225 v1(6329.86,6264.71) ; C168.1@6304.78,6210.89 cw(c6314.7,6200.97) 6314.7,6215 cw(c6314.7,6229.03) C168.1@6304.78,6219.11 ; v1@6325.97,6260.82 cw(c6316.58,6251.43) 6329.86,6251.43 cw(c6343.14,6251.43) v1@6333.75,6260.82 ; R255.1@6360.05,1236.25 ccw(c6350.95,1227.19) 6350.98,1240.03 ccw(c6351.01,1252.87) R255.1@6360.07,1243.77 ; 6456.86,5964.85 6457,5964.85 6459.33,5962.51 ; J29.4@6490.66,1365.61 cw(c6469.24,1341.15) v1@6501.75,1341.15 ; J29.4@6501.75,1359.3 ccw(c6526.78,1359.3) v1@6509.08,1341.6 ; J29.4@6501.75,1404.65 v1@6501.75,1341.15 ; v1(6505.19,1337.71) v1@6501.75,1341.15 ; J29.4@6512.84,1365.61 ccw(c6534.26,1341.15) v1@6501.75,1341.15 ; J30.4@6574.2,1166.63 ccw(c6545.46,1195.37) 6586.1,1195.37 ccw(c6626.74,1195.37) J30.4@6598,1166.63 ; J30.4@6586.1,1128.35 6586.1,1204.48 6590,1208.37 v1(6615.19,1208.37) ; v1@6611.3,1204.49 ccw(c6601.91,1195.1) 6601.91,1208.37 ccw(c6601.91,1221.65) v1@6611.3,1212.26 ; U14.11@6619.41,4655.75 6657.19,4655.75 6661.86,4660.41 6661.86,4660.71 v1(6665.19,4664.04) ; U14.11@6631.89,4655.75 ccw(c6631.89,4697.34) v1@6661.3,4667.93 ; R253.1@6686.18,1240 6710,1240 6720,1230 v1(6720,1210.19) v1@6720,1210 ; R253.1@6689.94,1236.24 cw(c6699.02,1227.16) 6699.02,1240 cw(c6699.02,1252.84) R253.1@6689.94,1243.76 ; C173.2@6700.67,5915 6721.86,5915 6723.52,5916.67 6723.52,5925.04 6740.19,5941.71 v1(6755.19,5941.71) ; v1(6702.52,4865.71) 6703.52,4866.71 6708.19,4871.38 C73.1@6735,4871.38 ; C173.2@6704.78,5910.89 cw(c6714.7,5900.97) 6714.7,5915 ; C173.2@6704.78,5919.11 ccw(c6714.7,5929.03) 6714.7,5915 ; v1@6706.41,4861.82 cw(c6729.49,4838.75) C73.1@6729.49,4871.38 ; v1@6716.11,1214.08 ccw(c6706.72,1223.47) 6720,1223.47 ccw(c6733.28,1223.47) v1@6723.89,1214.08 ; 6720.19,5921.71 cw(c6755.19,5886.72) v1@6755.19,5936.21 ; C71.1@6730.89,4453.36 ccw(c6720.97,4463.29) 6735,4463.29 ccw(c6749.03,4463.28) C71.1@6739.11,4453.36 ; C75.1@6730.89,4544.51 cw(c6720.97,4534.59) 6735,4534.59 cw(c6749.03,4534.6) 6739.11,4544.51 cw(c6749.03,4534.6) 6749.03,4548.62 cw(c6749.03,4562.65) C75.1@6739.11,4552.73 ; C77.1@6730.89,4685.22 cw(c6720.97,4675.3) 6735,4675.3 cw(c6749.03,4675.3) C77.1@6739.11,4685.22 ; C73.1@6730.89,4867.27 ccw(c6720.97,4857.35) 6720.97,4871.38 ccw(c6720.97,4885.41) C73.1@6730.89,4875.49 ; C71.1@6735,4449.26 6735,4474.85 ; C71.1@6735,4449.99 cw(c6776.24,4449.99) v1@6747.08,4479.15 ; 6735,4516.09 ccw(c6776.24,4516.09) v1@6747.08,4486.93 ; 6740.68,5942.2 cw(c6755.19,5927.69) v1@6755.19,5948.21 ; v1(6743.19,4483.04) 6735,4474.85 ; v1@6746.89,4662.44 cw(c6771.34,4689.33) C77.1@6735,4689.33 6735,4665.71 6742.67,4658.04 6742.86,4658.04 v1(6743.19,4658.37) 6767.07,4658.37 6806.86,4618.58 ; v1@6747.08,4654.49 cw(c6756.47,4645.1) 6756.47,4658.37 cw(c6756.47,4671.65) v1@6747.08,4662.26 ; v5(6795.66,6026.73) 6817.91,6048.98 6883.8,6048.98 v1(6885.19,6050.37) ; 6804.77,4616.5 cw(c6818.6,4602.67) U15.33@6826.43,4620.59 ; 6816.08,4627.81 cw(c6826.99,4616.91) U15.33@6829.16,4632.17 ; 6817.2,4628.93 cw(c6826.16,4619.97) U15.33@6831.24,4631.58 ; U15.33@6845.59,4624.25 6812.52,4624.25 6806.86,4618.58 ; C175.1@6862.31,6102.54 cw(c6814.14,6050.57) v1@6885,6050.57 ; 6868.56,6048.98 ccw(c6868.56,6067.01) 6881.3,6054.26 ccw(c6872.37,6063.19) 6885,6063.19 ; C175.1@6870.47,6111.34 cw(c6839.62,6078.06) 6885,6078.06 cw(c6930.38,6078.06) C175.1@6899.53,6111.34 ; v1(6882.52,1225.04) 6897.48,1240 R256.1@6923.82,1240 ; 6885,6064.11 ccw(c6898.93,6064.11) v1@6889.08,6054.26 ; C176.1@6891.56,5959.11 ccw(c6881.64,5969.03) 6895.67,5969.03 ccw(c6909.7,5969.03) C176.1@6899.78,5959.11 ; C177.1@6891.56,5995.89 cw(c6881.64,5985.97) 6895.67,5985.97 cw(c6909.7,5985.97) C177.1@6899.78,5995.89 ; C177.1@6891.56,6004.11 ccw(c6881.64,6014.03) 6895.67,6014.03 ccw(c6909.7,6014.03) C177.1@6899.78,6004.11 ; C176.1@6895.67,5955 C177.1@6895.67,6000 6895.67,6034.37 6898.34,6037.04 6898.34,6037.23 v1(6885.19,6050.37) ; C175.1@6907.69,6102.54 ccw(c6955.86,6050.57) v1@6885,6050.57 ; C175.1@6917.77,6110.21 cw(c6947.01,6093.17) 6947.01,6127.01 ; C175.1@6917.77,6143.81 ccw(c6947.01,6160.85) 6947.01,6127.01 ; R256.1@6920.06,1236.24 ccw(c6910.98,1227.16) 6910.98,1240 ccw(c6910.98,1252.84) R256.1@6920.06,1243.76 ; R251.1@7022.42,6134.25 ccw(c7013.34,6143.33) 7026.18,6143.33 ccw(c7039.02,6143.33) R251.1@7029.94,6134.25 ; R252.2@7022.42,6185.75 cw(c7013.34,6176.67) 7026.18,6176.67 cw(c7039.02,6176.67) R252.2@7029.94,6185.75 ; R252.2@7022.42,6194.25 ccw(c7013.34,6203.33) 7026.18,6203.33 ccw(c7039.02,6203.33) R252.2@7029.94,6194.25 ; R250.1@7022.42,6254.25 ccw(c7013.34,6263.33) 7026.18,6263.33 ccw(c7039.02,6263.33) R250.1@7029.94,6254.25 ; R250.1@7026.18,6250 7026.18,6271.18 v1(7030,6275) ; R250.1@7026.18,6252.5 cw(c7052.5,6252.5) v1@7033.89,6271.11 ; R251.1@7029.94,6126.24 cw(c7039.02,6117.16) 7039.02,6130 cw(c7039.02,6142.84) R251.1@7029.94,6133.76 ; v1@7144.64,1018.82 cw(c7135.25,1009.43) 7148.52,1009.43 cw(c7161.8,1009.43) v1@7152.41,1018.82 ; v1@7148.52,1016.12 ccw(c7179.44,1016.12) R115.2@7157.58,994.25 ; v1(7148.52,1022.71) 7148.52,995.29 R115.2@7153.82,990 ; NT45.1@7173.19,6112.13 ccw(c7156.54,6128.77) 7180.08,6128.77 ccw(c7203.61,6128.77) NT45.1@7186.97,6112.13 ; NT45.1@7180.08,6105.24 7180.08,6146.82 7160.19,6166.71 7095.86,6166.71 7059.19,6130.04 R251.1@7026.18,6130 R252.2@7026.18,6190 7026.18,6203.82 7016.63,6213.37 6968.52,6213.37 6958.52,6203.37 6958.52,6138.52 6947.01,6127.01 ; R113.1@7192.42,705.75 cw(c7183.34,696.67) 7196.18,696.67 cw(c7209.02,696.67) R113.1@7199.94,705.75 ; R114.1@7192.42,824.25 ccw(c7183.34,833.33) 7196.18,833.33 ccw(c7209.02,833.33) R114.1@7199.94,824.25 ; R113.1@7196.18,710 7196.18,673.82 7208.58,661.42 v5(7234.34,661.42) U19.17@7265.67,661.42 ; R114.1@7196.18,820 7196.18,846.48 7207.97,858.27 v5(7234.34,858.27) ; v1@7200.48,1322.96 ccw(c7182.56,1350) NT6.2@7215,1350 ; v1(7203.52,1318.37) 7215,1329.85 NT6.2@7215,1350 ; v1@7207.12,1312.96 ccw(c7197.38,1327.64) 7215,1327.64 ; v1(7246.19,4655.71) 7248.86,4655.71 U15.11@7294.41,4655.75 7305.37,4666.71 7371.86,4666.71 v1@7385,4653.56 ; v1@7250.08,4651.82 cw(c7259.56,4642.34) 7259.56,4655.75 ; v1@7250.08,4659.6 ccw(c7259.37,4668.89) 7259.37,4655.75 ; C95.1@7255.22,1110.89 cw(c7245.3,1100.97) 7259.33,1100.97 cw(c7273.36,1100.97) C95.1@7263.44,1110.89 ; C95.1@7259.33,1115 7259.33,1060.67 7274.33,1045.67 C91.2@7274.33,990 ; v1@7269.64,944.6 ccw(c7259.91,954.32) 7273.66,954.32 ; C91.2@7270.22,985.89 cw(c7261.91,977.58) 7273.66,977.58 ; C91.2@7270.22,994.11 ccw(c7260.3,1004.03) 7274.33,1004.03 ccw(c7288.36,1004.03) C91.2@7278.44,994.11 ; v1@7273.66,940.85 C91.2@7273.66,990 ; 7273.66,953.65 ccw(c7286.46,953.65) v1@7277.41,944.6 ; 7273.66,974.36 cw(c7289.97,974.36) C91.2@7278.44,985.89 ; v1@7279.97,540.49 cw(c7254.13,514.65) C94.1@7290.67,514.65 ; v1(7283.86,544.37) 7290.67,537.56 C94.1@7290.67,515 ; C94.1@7286.56,519.11 ccw(c7276.64,529.03) 7290.67,529.03 ccw(c7304.7,529.03) C94.1@7294.78,519.11 ; U15.11@7306.31,4661.4 cw(c7319.12,4648.6) 7319.12,4666.71 ; C93.1@7310.01,1341.35 cw(c7292.35,1311.53) 7327.01,1311.53 ; v1@7311.3,1278.93 ccw(c7301.91,1288.32) 7315.19,1288.32 ccw(c7328.47,1288.32) v1@7319.08,1278.93 ; U15.11@7314.8,4652.92 cw(c7348.09,4619.63) 7348.09,4666.71 ; v1(7315.19,1275.04) 7315.19,1299.71 7327.01,1311.52 ; C93.1@7327.01,1374 7327.01,1311.52 ; C93.1@7344.01,1341.35 ccw(c7361.66,1311.53) 7327.01,1311.53 ; C76.1@7380.89,4453.36 ccw(c7370.97,4463.29) 7385,4463.29 ccw(c7399.03,4463.28) C76.1@7389.11,4453.36 ; C72.1@7380.89,4685.22 cw(c7370.97,4675.3) 7385,4675.3 cw(c7399.03,4675.3) C72.1@7389.11,4685.22 ; 7381.93,4533.11 cw(c7368.69,4519.87) v1@7385.31,4511.24 ; C74.1@7382.58,4542.93 ccw(c7387.85,4555.32) 7397.37,4545.8 ; v1@7384.69,4648.37 ccw(c7371.41,4648.37) 7380.8,4657.76 ccw(c7390.19,4667.15) v1@7390.19,4653.87 ; C76.1@7385,4449.26 7385,4503.9 v1@7390,4508.9 ; 7385,4482.9 cw(c7416,4482.9) v1@7394.08,4504.82 ; C74.1@7385,4548.62 7396.86,4548.62 7398.52,4546.96 ; 7385,4674.18 ccw(c7416,4674.18) v1@7394.08,4652.26 ; C72.1@7385,4689.33 7385,4661.9 ; C78.1@7385,4830.04 7436.85,4830.04 v1(7442.52,4835.71) ; v1@7386.3,4512.6 ccw(c7377.37,4521.53) 7390,4521.53 ; C74.1@7387.27,4553.97 ccw(c7395.34,4572.97) 7409.94,4558.37 ; C74.1@7387.74,4543.5 cw(c7394.43,4531.01) 7404.45,4541.03 ; C78.1@7389.11,4825.93 cw(c7399.03,4816.01) 7399.03,4830.04 cw(c7399.03,4844.07) C78.1@7389.11,4834.15 ; 7390,4522.44 ccw(c7403.93,4522.44) v1@7394.08,4512.6 ; v1(7390.19,4508.71) v1@7390,4508.9 ; 7392.06,4522.98 cw(c7380.2,4511.12) v1@7396.51,4507.18 ; 7393.52,4521.53 cw(c7383.94,4511.95) v1@7395.96,4505.71 ; v1(7412.52,3454.37) v1@7419.86,3461.71 ; 7415.55,4830.04 ccw(c7415.55,4862.68) v1@7438.64,4839.6 ; C92.2@7416.56,994.11 ccw(c7406.64,1004.03) 7420.67,1004.03 ccw(c7434.7,1004.03) C92.2@7424.78,994.11 ; C92.2@7420.67,990 7420.67,1070.67 v1@7430,1080 ; 7420.67,1044.39 cw(c7465.8,1044.39) v1@7433.89,1076.3 ; 7420.67,1073.36 cw(c7436.83,1073.36) v1@7425.4,1084.79 ; v1@7446.64,4554.49 ccw(c7437.25,4545.1) 7437.25,4558.37 ccw(c7437.25,4571.65) v1@7446.64,4562.26 ; v1(7450.52,4558.37) 7409.94,4558.37 ; C90.2@7535.67,495 7595.67,495 7600,490.67 v1(7600,445) v1@7600,449.33 ; v1@7576.86,3456.04 v1(7576.86,3461.71) ; NT10.1@7592.87,1272.22 ccw(c7576.23,1288.87) 7599.76,1288.87 ccw(c7623.3,1288.86) NT10.1@7606.66,1272.22 ; v1@7594.64,1300.49 cw(c7582.25,1288.1) 7599.76,1288.1 ; v1@7596.11,448.89 ccw(c7586.72,458.28) 7600,458.28 ccw(c7613.28,458.28) v1@7603.89,448.89 ; v1(7598.52,1304.37) 7598.52,1309.04 7599.76,1310.28 7599.76,1304.37 NT10.1@7599.76,1255.08 ; R248.2@7667.56,1435.75 cw(c7658.48,1426.67) 7671.32,1426.67 cw(c7684.16,1426.67) R248.2@7675.08,1435.75 ; 7671.32,1421.98 ccw(c7692.13,1421.98) v1@7677.41,1407.26 ; R248.2@7671.32,1440 7671.32,1405.52 7672.65,1404.19 7672.86,1404.19 7672.86,1404.04 v1(7673.52,1403.37) ; v1@7700,3355 7731.86,3355 7736.72,3350.13 C222.1@7736.72,3296.18 ; v1@7703.89,3351.3 cw(c7712.81,3342.38) 7712.81,3355 ; v1@7703.89,3359.08 ccw(c7713.75,3368.94) 7713.75,3355 ; v1@7710,3440 7731.86,3440 7736.72,3435.13 C238.1@7736.72,3406.18 ; v1@7713.89,3436.3 cw(c7722.81,3427.38) 7722.81,3440 ; v1@7713.89,3444.08 ccw(c7723.75,3453.94) 7723.75,3440 ; U49.4@7718.66,1610.45 ccw(c7707.74,1621.38) 7723.19,1621.38 ; v1@7719.3,1652.82 cw(c7709.91,1643.43) 7723.19,1643.43 cw(c7736.47,1643.43) v1@7727.08,1652.82 ; U49.4@7723.19,1613.81 v1(7723.19,1656.71) ; 7723.19,1639.53 ccw(c7764.31,1639.53) U49.4@7735.23,1610.45 ; C222.1@7732.62,3300.29 ccw(c7722.7,3310.21) 7736.72,3310.21 ccw(c7750.75,3310.21) C222.1@7740.83,3300.29 ; C238.1@7732.62,3410.29 ccw(c7722.7,3420.21) 7736.72,3420.21 ccw(c7750.75,3420.21) C238.1@7740.83,3410.29 ; C228.1@7740.89,4682.11 ccw(c7730.97,4692.03) 7745,4692.03 ccw(c7759.03,4692.03) C228.1@7749.11,4682.11 ; C227.1@7745,4788 7786.19,4788 7786.23,4788 C247.1@7843.66,4788 ; C227.1@7749.11,4783.89 cw(c7759.03,4773.97) 7759.03,4788 cw(c7759.03,4802.03) C227.1@7749.11,4792.11 ; C228.1@7750.81,4678 ccw(c7787.2,4678) 7761.47,4652.27 ; v2@7764.26,4642.48 ccw(c7747.36,4642.48) 7759.31,4654.43 ccw(c7771.26,4666.38) v2@7771.26,4649.48 ; v2(7771.26,4642.48) 7740.37,4673.37 C228.1@7745,4678 7745,4700 7756.71,4711.71 v1(7795.19,4711.71) ; 7772.81,4788 ccw(c7772.81,4801.42) v1@7782.3,4791.93 ; 7773.01,4788 cw(c7773.01,4774.86) v1@7782.3,4784.15 ; v1@7790.08,4784.15 cw(c7799.37,4774.86) 7799.37,4788 ; v1@7790.08,4791.93 ccw(c7799.57,4801.42) 7799.57,4788 ; v1@7791.3,4707.82 ccw(c7781.91,4698.43) 7781.91,4711.71 ccw(c7781.91,4724.99) v1@7791.3,4715.6 ; C247.1@7839.55,4792.11 cw(c7829.63,4802.03) 7829.63,4788 cw(c7829.63,4773.97) 7839.55,4783.89 cw(c7829.63,4773.97) 7843.66,4773.97 cw(c7857.69,4773.97) C247.1@7847.77,4783.89 ; C247.1@7843.66,4788 7843.66,4751.34 7846.75,4748.25 7883.25,4748.25 7890.02,4741.48 7890.02,4683.02 C248.1@7885,4678 ; C254.1@7872.62,3300.29 ccw(c7862.7,3310.21) 7876.72,3310.21 ccw(c7890.75,3310.21) C254.1@7880.83,3300.29 ; v1(7872.86,2225.04) 7877.9,2220 R39.1@7908.82,2220 ; v1@7876.75,2228.93 ccw(c7898.31,2250.49) R39.1@7898.31,2220 ; C254.1@7876.72,3296.18 7876.72,3328.24 v1(7906.86,3358.37) ; C253.1@7880.83,3402.07 cw(c7890.75,3392.15) 7890.75,3406.18 cw(c7890.75,3420.21) C253.1@7880.83,3410.29 ; C248.1@7880.89,4682.11 ccw(c7858.84,4704.16) 7890.02,4704.16 ; 7899.28,3406.18 ccw(c7899.28,3421.81) v1@7912.25,3413.08 ; v1@7901.36,3358.37 cw(c7888.08,3358.37) 7897.47,3348.99 cw(c7906.86,3339.6) v1@7906.86,3352.87 ; v1@7902.3,3419.78 cw(c7876.73,3437.01) C253.1@7876.72,3406.18 7896.33,3406.18 v1(7906.86,3416.71) ; R39.1@7905.06,2216.24 ccw(c7895.98,2207.16) 7895.98,2220 ccw(c7895.98,2232.84) R39.1@7905.06,2223.76 ; C39.2@7946.56,2514.11 ccw(c7936.64,2524.03) 7950.67,2524.03 ccw(c7964.7,2524.03) C39.2@7954.78,2514.11 ; R161.1@7947.9,1878.66 cw(c7954.28,1867.34) 7963.47,1876.53 ; C39.2@7950.67,2510 7950.67,2545 7956.38,2550.71 v1(7975.86,2550.71) ; R162.1@7951.18,1765 7975,1765 7985,1775 v1(7985,1795.19) ; R161.1@7951.18,1867.52 cw(c7951.18,1816.11) 7987.54,1852.46 ; R161.1@7951.18,1873.33 7966.67,1873.33 7985,1855 v1(7985,1795.19) ; R161.1@7951.18,1879.52 cw(c7951.18,1857.08) 7967.05,1872.95 ; R161.1@7953.79,1868.21 cw(c7962.34,1853.03) 7974.66,1865.34 ; R162.1@7954.94,1761.24 cw(c7964.02,1752.16) 7964.02,1765 cw(c7964.02,1777.84) R162.1@7954.94,1768.76 ; R161.1@7954.94,1869.57 cw(c7964.02,1860.49) 7964.02,1873.33 cw(c7964.02,1886.17) R161.1@7954.94,1877.09 ; v1@7968.64,2402.93 ccw(c7959.25,2412.32) 7972.52,2412.32 ccw(c7985.8,2412.32) v1@7976.41,2402.93 ; U4.5@7971.51,2451.01 cw(c7981.43,2441.09) 7981.43,2455.12 cw(c7981.43,2469.15) U4.5@7971.51,2459.23 ; v1@7971.97,2546.82 ccw(c7962.58,2537.43) 7962.58,2550.71 ccw(c7962.58,2563.99) v1@7971.97,2554.6 ; v1@7981.11,1791.3 cw(c7971.72,1781.92) 7985,1781.92 cw(c7998.28,1781.92) v1@7988.89,1791.3 ; v1@7981.11,1799.08 ccw(c7971.72,1808.47) 7985,1808.47 ccw(c7998.28,1808.47) v1@7988.89,1799.08 ; v1@7985,1795 v1(7985,1795.19) ; v1@8044.69,2485.04 cw(c8031.41,2485.04) 8040.8,2475.65 cw(c8050.19,2466.26) v1@8050.19,2479.54 ; v1@8046.3,2488.93 ccw(c8036.91,2498.32) 8050.19,2498.32 ccw(c8063.47,2498.32) v1@8054.08,2488.93 ; R131.2@8070.06,2506.24 ccw(c8060.98,2497.16) 8060.98,2510 ccw(c8060.98,2522.84) R131.2@8070.06,2513.76 ; R131.2@8073.82,2510 8055,2510 8050.19,2505.19 v1(8050.19,2485.04) 8020.27,2455.12 U4.5@7967.4,2455.12 7967.4,2425 7972.52,2419.88 v1@7972.52,2400.92 ; -354.99,2714.99 -349.93,2720.04 -340,2720.04 ; v1@2975,5717.52 v1(2975.19,5717.71) v1@2975,5717.52 ; v1@4001.73,5586.17 v1(4004.52,5583.37) v1@4001.73,5586.17 ; 4961.8,2641.71 cw(c4961.8,2654.99) 4952.41,2645.6 ccw(c4961.8,2654.99) 4961.8,2641.71 ; 4961.8,2641.71 ccw(c4961.8,2628.43) 4952.41,2637.82 cw(c4961.8,2628.43) 4961.8,2641.71 ; 6735,4474.85 6735,4483.04 C75.1@6735,4548.62 6779.19,4548.62 6780.52,4549.96 6780.52,4550.04 6781.86,4550.04 6806.86,4575.04 6806.86,4618.58 ; v1@6885,6050.56 C175.1@6885,6127.01 6947.01,6127.01 ; v1@6885,6050.56 v1(6885.19,6050.37) ; 7385,4534.6 cw(c7399.03,4534.6) 7389.11,4544.51 ccw(c7399.03,4534.6) 7385,4534.6 ; 7385,4534.59 ccw(c7370.97,4534.59) 7380.89,4544.51 cw(c7370.97,4534.59) 7385,4534.59 ; v1@7385,4653.56 v1(7390.19,4648.37) 7390.19,4656.71 7385,4661.9 ; v1@7385,4653.56 7385,4661.9 ; v1@7390,4508.9 7390,4525.04 7385,4530.04 7385,4533.43 7392.6,4541.03 7398.52,4546.96 ; 7398.52,4546.96 7409.94,4558.37 ; 7967.4,2428.29 cw(c7981.43,2428.29) 7971.51,2438.21 ccw(c7981.43,2428.29) 7967.4,2428.29 ; 7967.4,2428.29 ccw(c7953.37,2428.29) 7963.29,2438.21 cw(c7953.37,2428.29) 7967.4,2428.29 ; v1@7972.52,2400.92 7973.4,2400.04 v1(7972.52,2399.04) v1@7972.52,2400.92
  other v1: 6325,1010 7430,1080.19 7387.19,1381.71 410,1450 2480,1450 168,1461.51 193,1461.51 2835,1462.5 2890.83,1462.5 2191.14,1465 2295,1465 2835,1485 2890.83,1485 168,1487.5 193,1487.5 2191.14,1487.5 2295,1487.5 375,1490 445,1490 2445,1490 2515,1490 2835,1507.5 2890.83,1507.5 2191.14,1510 2295,1510 168,1513.5 193,1513.5 375,1516.67 445,1516.67 2445,1516.67 2515,1516.67 168,1539.5 193,1539.5 375,1543.33 445,1543.33 2445,1543.33 2515,1543.33 375,1570 445,1570 2445,1570 2515,1570 195,1585 165,1601.02 345,1605 371,1605 445,1605 471,1605 165,1627.01 345,1630 371,1630 445,1630 471,1630 165,1653.01 345,1655 371,1655 445,1655 471,1655 165,1679 680,1690.02 769.51,1702.91 792.01,1702.91 165,1705 5723.52,1709.04 680,1716.02 705.01,1716.06 165,1731 680,1742.01 705.01,1742.05 165,1756.99 680,1768.01 705.01,1768.05 165,1782.99 680,1794 705.01,1794.04 165,1808.98 680,1820 705.01,1820.04 747.01,1824.96 769.51,1824.96 792.01,1824.96 165,1834.98 680,1846 705.01,1846.04 4633,1851 165,1860.98 21.14,1885 125,1885 21.14,1907.5 125,1907.5 165,1919 21.14,1930 125,1930 165,1945 680,1949.98 705,1950.02 165,1971 680,1975.98 705,1976.02 165,1999 679.99,2001.97 705,2002.01 165,2025 679.99,2027.97 705,2028.01 165,2051 679.99,2053.96 705,2054 679.99,2079.96 705,2080 220,2145 246,2145 315,2145 341,2145 366.99,2145 392.99,2145 418.98,2145 444.98,2145 470.98,2145 496.97,2145.01 522.97,2145.01 548.96,2145.01 574.96,2145.01 220,2175 246,2175 315,2175 341,2175 366.99,2175 392.99,2175 418.98,2175 444.98,2175 470.98,2175 496.97,2175.01 522.97,2175.01 548.96,2175.01 574.96,2175.01 7881.86,2285.71 7340,2355 5360.19,2641.71 8140,2905.19 776.83,3143.04 808.33,3143.04 7700,3355.19 7710,3440.19 8027.52,3882.23 7786.19,4788.04 7573.52,4920.04 4033.82,5516.37 3045,5675.19
  other v4: 5785,5665 6455,5980
3V3A: C53.2 L2.2 U5.36 | length 1127.5
  MidLayer2 w12: v1(2489.52,5733.37) 2842.52,5733.37 v1(2906.86,5669.04) ; v1@2493.41,5729.49 cw(c2502.8,5720.1) 2502.8,5733.37 cw(c2502.8,5746.65) v1@2493.41,5737.26 ; v1@2901.36,5669.04 ccw(c2888.08,5669.04) 2897.47,5678.43 ccw(c2906.86,5687.82) v1@2906.86,5674.54
  Bottom Layer w12: U5.36@2469.13,5657.32 2469.13,5712.98 v1(2489.52,5733.37) ; v1@2484.02,5733.37 cw(c2470.75,5733.37) 2480.14,5723.99 cw(c2489.52,5714.6) v1@2489.52,5727.87 ; v1@2902.97,5665.15 cw(c2893.58,5655.76) 2906.86,5655.76 cw(c2920.14,5655.76) v1@2910.75,5665.15 ; v1(2906.86,5669.04) 2906.86,5608.37 2930.12,5585.12 3024.88,5585.12 3054.06,5555.94 L2.2@3125,5555.94 3145.67,5535.28 C53.2@3145.67,5500 ; L2.2@3085.8,5546.27 ccw(c3062.43,5522.91) 3062.43,5555.94 ccw(c3062.43,5588.98) L2.2@3085.8,5565.62 ; C53.2@3141.56,5504.11 ccw(c3131.64,5514.03) 3145.67,5514.03 ccw(c3159.7,5514.03) C53.2@3149.78,5504.11 ; C53.2@3145.67,5501.52 cw(c3208.95,5501.52) L2.2@3164.2,5546.27 ; 3145.67,5530.49 cw(c3179.98,5530.49) L2.2@3155.72,5554.75
3V3SET: R205.1 R206.1 U41.1 | length 445.6
  Bottom Layer w4: U41.1@510,1525 U41.1@510.04,1525.04
  Bottom Layer w12: U41.1@510,1525 545,1560 710,1560 741.18,1591.18 R205.1@741.18,1625 R206.1@833.82,1625 ; R205.1@737.42,1620.75 cw(c728.34,1611.67) 741.18,1611.67 cw(c754.02,1611.67) R205.1@744.94,1620.75 ; R205.1@744.94,1621.24 cw(c754.02,1612.16) 754.02,1625 cw(c754.02,1637.84) R205.1@744.94,1628.76 ; R206.1@830.06,1621.24 ccw(c820.98,1612.16) 820.98,1625 ccw(c820.98,1637.84) R206.1@830.06,1628.76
